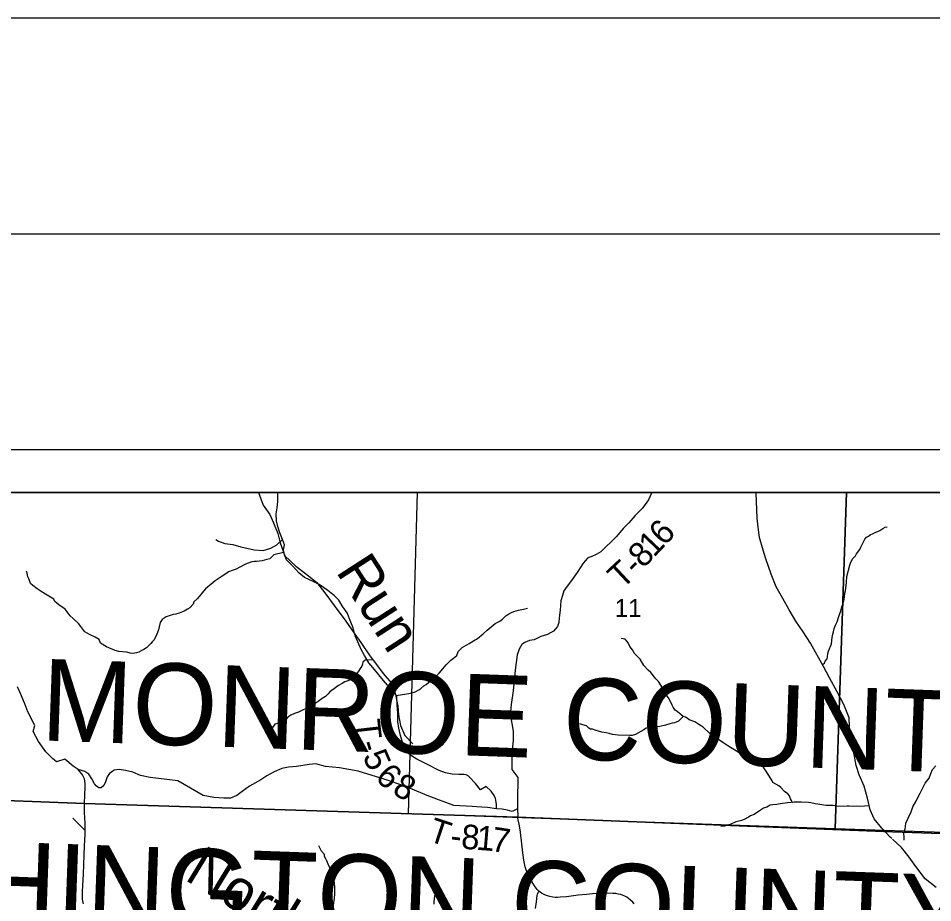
# Model space of a CAD drawing. Extents: x 6.3 to 40.3, y 9 to 31.
# Drawn here: x 10.464 to 12.585, y 28.995 to 31.046 of the extents above; entities that cross this region are included whole.
import ezdxf

# ---------------------------------------------------------------- set-up
doc = ezdxf.new("R2010")
doc.units = 0
for name, color, linetype in [('Default', 7, 'Continuous'), ('GM_X_Corporation', 7, 'Continuous'), ('GM_X_County_Text', 7, 'Continuous'), ('GM_X_Minor_River', 7, 'Continuous'), ('GM_X_Minor_River_Text', 7, 'Continuous'), ('GM_X_Section_Text', 7, 'Continuous'), ('GM_X_Township_Road', 7, 'Continuous'), ('GM_X_Township_Road_Text', 7, 'Continuous'), ('SH_Border', 7, 'Continuous'), ('SH_Cut_Line', 7, 'Continuous'), ('SH_Data', 7, 'Continuous')]:
    doc.layers.add(name, color=color, linetype=linetype)

msp = doc.modelspace()

# ---------------------------------------------------------------- linework, layer by layer
at = {"layer": 'Default'}
for points in [[(13.1323, 29.9457), (8.4446, 29.9457), (8.4446, 27.9161), (8.9627, 27.9002), (9.9314, 27.8681), (10.145, 27.8635), (10.7129, 27.8423), (11.7175, 27.8106), (12.5872, 27.7766), (13.0625, 27.76), (13.0974, 28.6191), (13.1136, 29.1637), (13.1156, 29.231), (13.116, 29.2473), (13.13, 29.8856)], [(12.9998, 29.9457), (8.4446, 29.9457), (8.4446, 29.2958), (8.8673, 29.2829), (9.8361, 29.2507), (10.0496, 29.2462), (10.6176, 29.225), (11.6221, 29.1933), (12.4918, 29.1593), (12.9672, 29.1426)]]:
    msp.add_lwpolyline(points, close=True, dxfattribs=at)
msp.add_lwpolyline([(12.9672, 29.1426), (12.4918, 29.1593), (11.6221, 29.1933), (10.6176, 29.225), (10.0496, 29.2462), (9.8361, 29.2507), (8.8673, 29.2829), (8.4446, 29.2958), (8.4446, 23.1457)], dxfattribs=at)
at = {"layer": 'GM_X_Corporation'}
for points in [[(12.3853, 29.9457), (11.3893, 29.9457), (11.3683, 29.2019), (12.3591, 29.1669)], [(13, 29.9457), (12.3853, 29.9457), (12.3591, 29.1669), (12.9779, 29.1462), (12.9985, 29.8988)]]:
    msp.add_lwpolyline(points, close=True, dxfattribs=at)
at = {"layer": 'GM_X_Minor_River'}
for points in [[(11.0214, 29.9457), (11.0322, 29.9167), (11.0478, 29.8951), (11.0565, 29.8759), (11.0667, 29.851), (11.0716, 29.8295), (11.0826, 29.7993), (11.1083, 29.7755), (11.1303, 29.7585), (11.1568, 29.737), (11.178, 29.7105), (11.1973, 29.6837), (11.2238, 29.6475), (11.245, 29.6177), (11.2586, 29.5981), (11.2798, 29.5675), (11.2953, 29.5471), (11.3105, 29.5263), (11.3301, 29.5037), (11.3396, 29.4772), (11.3449, 29.4504), (11.346, 29.4304), (11.3506, 29.4055), (11.3612, 29.3821), (11.3797, 29.3629)], [(12.2376, 29.7003), (12.222, 29.7275), (12.2103, 29.7566), (12.1982, 29.7924), (12.1921, 29.8121), (12.1831, 29.8419), (12.18, 29.8657), (12.1778, 29.8864), (12.1759, 29.9446), (12.1759, 29.9457)], [(12.3298, 29.5468), (12.3338, 29.5506), (12.336, 29.5552), (12.34, 29.5606), (12.3414, 29.5648), (12.3416, 29.5724), (12.3434, 29.5782), (12.3502, 29.5954), (12.3518, 29.6099), (12.3536, 29.6172), (12.355, 29.6225), (12.3567, 29.6309), (12.3599, 29.6382), (12.3636, 29.6463), (12.3664, 29.6558), (12.3689, 29.6627), (12.3717, 29.6715), (12.3742, 29.6811), (12.3767, 29.6868), (12.3792, 29.6945), (12.3805, 29.7036), (12.3811, 29.7124), (12.3829, 29.7177), (12.3855, 29.7372), (12.3863, 29.7509), (12.3926, 29.7772), (12.3943, 29.7818), (12.3994, 29.7922), (12.4057, 29.7988), (12.4083, 29.8038), (12.416, 29.8139), (12.4182, 29.8196), (12.424, 29.83), (12.4276, 29.8381), (12.4317, 29.8427), (12.4362, 29.8451), (12.4403, 29.8478), (12.4467, 29.8506), (12.4531, 29.8538), (12.4576, 29.8558), (12.4625, 29.8582), (12.4696, 29.8629), (12.4745, 29.8653), (12.4798, 29.8666)], [(11.0798, 29.8069), (11.0569, 29.8012), (11.048, 29.7923), (11.0405, 29.7906), (11.0299, 29.7877), (11.0235, 29.7864), (11.017, 29.7862), (11.0114, 29.7857), (11.0061, 29.7849), (10.991, 29.78), (10.9786, 29.7728), (10.9696, 29.7685), (10.9602, 29.7652), (10.9523, 29.762), (10.9456, 29.7577), (10.9351, 29.7506), (10.9306, 29.7475), (10.9213, 29.7408), (10.9116, 29.7337), (10.8989, 29.7228), (10.8937, 29.717), (10.8837, 29.7046), (10.8793, 29.6992), (10.8719, 29.6926), (10.8697, 29.6872), (10.8623, 29.6787), (10.8571, 29.6751), (10.8492, 29.6708), (10.8375, 29.6663), (10.8296, 29.6639), (10.8239, 29.663), (10.8123, 29.6589), (10.8077, 29.6577), (10.798, 29.6518), (10.7936, 29.6448), (10.7915, 29.6345), (10.7894, 29.6273), (10.7855, 29.6177), (10.7797, 29.6042), (10.7748, 29.6), (10.7715, 29.5957), (10.7667, 29.5903), (10.7619, 29.586), (10.7559, 29.5821), (10.7495, 29.5785), (10.7439, 29.5757), (10.7386, 29.5741), (10.7344, 29.5732), (10.7295, 29.5727), (10.7238, 29.5737), (10.7158, 29.5755), (10.7063, 29.5764), (10.6976, 29.577), (10.6892, 29.5794), (10.6692, 29.5881), (10.655, 29.5969), (10.6522, 29.6052), (10.6426, 29.6103), (10.6299, 29.6169), (10.6191, 29.6227), (10.6098, 29.635), (10.6039, 29.6421), (10.5915, 29.6536), (10.5849, 29.6599), (10.5728, 29.6756), (10.5586, 29.6852), (10.5489, 29.6933), (10.5465, 29.6986), (10.5273, 29.7103), (10.5153, 29.7176), (10.508, 29.7224), (10.4984, 29.7302), (10.493, 29.735), (10.4897, 29.744), (10.4865, 29.7508), (10.4848, 29.7591), (10.4832, 29.7633)], [(12.4901, 29.1437), (12.4866, 29.1469), (12.4669, 29.1677), (12.4495, 29.1896), (12.4401, 29.21), (12.4336, 29.2375), (12.4261, 29.2651), (12.4143, 29.2911), (12.4075, 29.3126), (12.4033, 29.3383), (12.3969, 29.3697), (12.3924, 29.4025), (12.3916, 29.4233), (12.3791, 29.4546), (12.3636, 29.484), (12.3458, 29.5165), (12.3322, 29.5426), (12.3019, 29.5969), (12.2849, 29.623), (12.2678, 29.6475), (12.2519, 29.6739), (12.2376, 29.7003)], [(11.34, 29.4754), (11.3396, 29.4751), (11.3453, 29.4763), (11.351, 29.4768), (11.36, 29.4782), (11.3699, 29.4799), (11.3804, 29.4824), (11.385, 29.4837), (11.3936, 29.488), (11.3981, 29.4916), (11.4048, 29.4974), (11.4104, 29.5006), (11.4167, 29.5064), (11.4234, 29.5119), (11.4309, 29.5178), (11.4406, 29.5267), (11.4494, 29.5372), (11.4564, 29.5465), (11.4628, 29.5527), (11.4676, 29.5573), (11.4736, 29.562), (11.4818, 29.5683), (11.4842, 29.5775), (11.4939, 29.5864), (11.5104, 29.5959), (11.5201, 29.6018), (11.5291, 29.6074), (11.5422, 29.6179), (11.5518, 29.6269), (11.5701, 29.6425), (11.5813, 29.648), (11.5877, 29.6524), (11.5951, 29.6601), (11.6022, 29.6649), (11.6082, 29.6677), (11.6135, 29.6697), (11.6188, 29.6713), (11.6244, 29.673), (11.6286, 29.6738), (11.6358, 29.6755), (11.6456, 29.678)], [(12.2598, 29.2274), (12.2593, 29.2271), (12.2573, 29.2316), (12.2557, 29.2357), (12.2529, 29.2429), (12.2494, 29.247), (12.2416, 29.2525), (12.2327, 29.2618), (12.2281, 29.2655), (12.2146, 29.2736), (12.2126, 29.2777), (12.2024, 29.2934), (12.1981, 29.3009), (12.1895, 29.3137), (12.1752, 29.3228), (12.1683, 29.3265), (12.1633, 29.3298), (12.1418, 29.3384), (12.1364, 29.3425), (12.1099, 29.3582), (12.1007, 29.3645), (12.0953, 29.3682), (12.0733, 29.3821), (12.0671, 29.3877), (12.0528, 29.4018), (12.0486, 29.404), (12.0424, 29.4076), (12.0335, 29.4143), (12.0205, 29.4189), (12.0159, 29.4226), (12.0117, 29.4248), (12.0067, 29.4262), (11.9974, 29.434), (11.9928, 29.4384), (11.9878, 29.441), (11.9831, 29.4481), (11.9811, 29.453), (11.9743, 29.4673), (11.97, 29.4729), (11.9617, 29.4871), (11.9582, 29.4931), (11.9495, 29.5078), (11.9433, 29.5141), (11.9312, 29.5286), (11.925, 29.5342), (11.9149, 29.545), (11.9066, 29.5596), (11.9031, 29.5637), (11.8934, 29.5726), (11.8887, 29.5812), (11.8825, 29.5891), (11.8785, 29.597), (11.8761, 29.6011), (11.8722, 29.6056), (11.8676, 29.607), (11.8623, 29.6076)], [(11.287, 29.558), (11.2687, 29.5571), (11.2632, 29.5524), (11.2625, 29.5478), (11.2615, 29.5432), (11.2574, 29.5378), (11.2534, 29.5316), (11.2486, 29.5255), (11.2393, 29.5158), (11.2341, 29.5118), (11.2288, 29.5094), (11.222, 29.5066), (11.2157, 29.5034), (11.207, 29.4987), (11.2018, 29.4948), (11.1973, 29.4909), (11.1932, 29.4881), (11.1872, 29.4838), (11.1828, 29.4788), (11.1769, 29.4733), (11.1694, 29.4682), (11.1597, 29.4611), (11.1503, 29.4552), (11.1417, 29.4505), (11.1319, 29.4449), (11.1222, 29.4405), (11.1139, 29.4369), (11.1052, 29.4337), (11.0966, 29.4297), (11.0899, 29.425), (11.0854, 29.4203), (11.0738, 29.4136), (11.0689, 29.4112), (11.0595, 29.4084), (11.0506, 29.3964), (11.0485, 29.3918), (11.0463, 29.3875), (11.0438, 29.3822)], [(12.0061, 29.4267), (11.9959, 29.4161), (11.9903, 29.4133), (11.9861, 29.4121), (11.9809, 29.4108), (11.9752, 29.4095), (11.9658, 29.4063), (11.9526, 29.4033), (11.9461, 29.4024), (11.9367, 29.4011), (11.9325, 29.401), (11.9204, 29.3992), (11.9148, 29.3956), (11.896, 29.385), (11.8881, 29.3825), (11.8828, 29.3824), (11.8559, 29.3833), (11.8425, 29.3849), (11.8345, 29.387), (11.8276, 29.3887), (11.8177, 29.3904), (11.8101, 29.3929), (11.8048, 29.3943), (11.796, 29.3968), (11.7918, 29.3974), (11.7876, 29.3996), (11.7821, 29.4048), (11.7734, 29.4073), (11.7691, 29.4087), (11.7634, 29.4097)], [(12.5193, 29.1398), (12.5187, 29.1463), (12.5185, 29.1561), (12.5196, 29.1603), (12.521, 29.1661), (12.522, 29.171), (12.5226, 29.1802), (12.5273, 29.1883), (12.5287, 29.1932), (12.5342, 29.2028), (12.5392, 29.217), (12.5476, 29.2317), (12.5502, 29.237), (12.5563, 29.2489), (12.5647, 29.2659), (12.5676, 29.2716), (12.5772, 29.2836), (12.5811, 29.2947), (12.5844, 29.3035), (12.5921, 29.3125)], [(12.4378, 29.2197), (12.4158, 29.2177), (12.4082, 29.2183), (12.4018, 29.2181), (12.3915, 29.2183), (12.3866, 29.2185), (12.3665, 29.2181), (12.3543, 29.2201), (12.3482, 29.2199), (12.338, 29.2205), (12.333, 29.2211), (12.3189, 29.2235), (12.3125, 29.2241), (12.3026, 29.2261), (12.2972, 29.2272), (12.2798, 29.2275), (12.2726, 29.2277), (12.2642, 29.2279), (12.2559, 29.227), (12.2487, 29.2261), (12.2313, 29.2241), (12.2237, 29.2228), (12.2146, 29.2215), (12.2082, 29.2206), (12.2003, 29.2166), (12.1924, 29.2142), (12.1834, 29.2079), (12.1711, 29.1996), (12.1628, 29.1964), (12.1583, 29.1932), (12.1478, 29.1877), (12.1418, 29.1853), (12.1354, 29.1836), (12.1286, 29.1823), (12.1154, 29.1759), (12.1083, 29.1743), (12.1026, 29.1726), (12.0984, 29.1721), (12.0939, 29.1713)], [(12.5934, 29.0302), (12.5676, 29.0502), (12.546, 29.0789), (12.5305, 29.1005), (12.5127, 29.1227), (12.4916, 29.1423)], [(11.1949, 28.983), (11.1959, 28.9948), (11.197, 29.0002), (11.1977, 29.0055), (11.1984, 29.0154), (11.1986, 29.0294), (11.1974, 29.0408), (11.1954, 29.0495), (11.1938, 29.0552), (11.1926, 29.0594), (11.1903, 29.0666), (11.1867, 29.0756), (11.1829, 29.0843), (11.1797, 29.0915), (11.1774, 29.0968), (11.1747, 29.1021), (11.1743, 29.1067), (11.1674, 29.1142), (11.1611, 29.1263)], [(11.4288, 28.9916), (11.4291, 28.9969), (11.4304, 29.011), (11.4334, 29.022), (11.4348, 29.0304), (11.4344, 29.0346), (11.4339, 29.0391), (11.432, 29.0441), (11.43, 29.049), (11.4257, 29.0626)]]:
    msp.add_lwpolyline(points, dxfattribs=at)
at = {"layer": 'GM_X_Township_Road'}
for points in [[(11.5736, 29.2127), (11.5734, 29.2234), (11.5715, 29.2366), (11.5684, 29.2436), (11.561, 29.2535), (11.5499, 29.2642), (11.536, 29.2564), (11.5245, 29.2708), (11.512, 29.2852), (11.5081, 29.2891), (11.5033, 29.291), (11.4976, 29.292), (11.4861, 29.292), (11.4707, 29.2929), (11.4553, 29.2958), (11.4409, 29.3016), (11.4102, 29.3169), (11.3891, 29.3275), (11.3766, 29.3352), (11.367, 29.3419), (11.3603, 29.3535), (11.3564, 29.364), (11.3507, 29.3823), (11.3468, 29.3996), (11.3449, 29.4149), (11.3449, 29.4341), (11.343, 29.4533), (11.342, 29.4726), (11.3372, 29.4822), (11.3295, 29.4899), (11.3209, 29.4995), (11.3113, 29.51), (11.3007, 29.5235), (11.2863, 29.5398), (11.2777, 29.5513), (11.2671, 29.5677), (11.2594, 29.5821), (11.2518, 29.5994), (11.246, 29.6138), (11.2412, 29.632), (11.2354, 29.6455), (11.2268, 29.6666), (11.2172, 29.681), (11.2076, 29.6964), (11.198, 29.706), (11.1826, 29.7185), (11.1625, 29.7329), (11.148, 29.7396), (11.1279, 29.7492), (11.1154, 29.7598), (11.101, 29.7751), (11.0866, 29.7895), (11.0818, 29.8011), (11.0798, 29.8131), (11.0818, 29.8246), (11.077, 29.8371), (11.0712, 29.8525), (11.0664, 29.8669), (11.0635, 29.8803), (11.0626, 29.8967), (11.0645, 29.9101), (11.0664, 29.9255), (11.0664, 29.9428), (11.0653, 29.9457)], [(11.9337, 29.9457), (11.9261, 29.9292), (11.9123, 29.9093), (11.8954, 29.8925), (11.8801, 29.8756), (11.8678, 29.8633), (11.851, 29.8434), (11.8158, 29.8082), (11.805, 29.802), (11.7943, 29.7974), (11.7851, 29.7944), (11.7744, 29.7821), (11.7606, 29.7607), (11.7453, 29.7392), (11.7376, 29.7285), (11.7299, 29.7178), (11.7269, 29.707), (11.7223, 29.6948), (11.7208, 29.6733), (11.7192, 29.655), (11.7177, 29.6442), (11.7146, 29.635), (11.7054, 29.6243), (11.6916, 29.6166), (11.6763, 29.6121), (11.661, 29.6044), (11.6503, 29.6028), (11.6395, 29.5983), (11.6319, 29.5937), (11.6258, 29.5829), (11.6211, 29.5692), (11.6166, 29.5339), (11.612, 29.4864), (11.6074, 29.4542), (11.6058, 29.4373), (11.6074, 29.419), (11.6104, 29.4021), (11.612, 29.3914), (11.612, 29.3715), (11.6089, 29.3393), (11.6089, 29.304), (11.6226, 29.285), (11.6218, 29.2315), (11.6224, 29.2121), (11.6232, 29.1956), (11.6223, 29.1928)], [(10.9222, 29.8373), (10.9288, 29.8334), (10.9433, 29.8275), (10.9617, 29.8255), (10.9808, 29.8202), (11.0117, 29.813), (11.0327, 29.8117), (11.0505, 29.8169), (11.0643, 29.8248), (11.077, 29.8371)], [(11.6224, 29.2121), (11.6102, 29.2066), (11.5993, 29.2092), (11.5864, 29.2117), (11.5736, 29.2127), (11.5528, 29.2152), (11.5392, 29.2166), (11.5277, 29.2173), (11.5172, 29.2177), (11.4743, 29.22), (11.4167, 29.2418), (11.3606, 29.2652), (11.3154, 29.2808), (11.253, 29.2995), (11.2094, 29.3073), (11.1766, 29.3104), (11.1548, 29.3167), (11.1392, 29.3151), (11.1096, 29.3104), (11.0909, 29.3089), (11.0753, 29.3058), (11.0582, 29.2979), (11.041, 29.2886), (11.027, 29.2793), (11.0005, 29.2652), (10.9833, 29.2528), (10.9709, 29.2434), (10.9569, 29.2371), (10.9413, 29.2371), (10.9179, 29.2387), (10.8929, 29.2434), (10.8346, 29.2773), (10.8086, 29.2806), (10.77, 29.2853), (10.748, 29.29), (10.73, 29.2976), (10.713, 29.3013), (10.6983, 29.3036), (10.687, 29.302), (10.676, 29.294), (10.6707, 29.2863), (10.6667, 29.275), (10.6627, 29.2666), (10.6567, 29.261), (10.6513, 29.261), (10.6448, 29.2654), (10.6413, 29.2703), (10.6347, 29.2823), (10.628, 29.2926), (10.619, 29.299), (10.6033, 29.3036), (10.592, 29.3113), (10.572, 29.3276), (10.5532, 29.3214), (10.5438, 29.3292), (10.5282, 29.3448), (10.5111, 29.3682), (10.4986, 29.3916), (10.5026, 29.406), (10.4866, 29.4374), (10.4794, 29.4558), (10.4695, 29.4797), (10.4623, 29.4955)], [(10.6178, 29.2245), (10.6187, 29.245), (10.6197, 29.2626), (10.6197, 29.2713), (10.618, 29.282), (10.6133, 29.2913), (10.6033, 29.3036)], [(10.6196, 29.1623), (10.6195, 29.1704), (10.6193, 29.1797), (10.6186, 29.1908), (10.6177, 29.2049), (10.6176, 29.2142), (10.6178, 29.2245)], [(10.5913, 29.1905), (10.6025, 29.1788), (10.6189, 29.1629), (10.6196, 29.1623)], [(11.6713, 29.0217), (11.668, 29.0251), (11.6653, 29.0284), (11.6614, 29.034), (11.6574, 29.0404), (11.651, 29.0517), (11.6476, 29.0583), (11.6448, 29.0646), (11.6425, 29.071), (11.6403, 29.0782), (11.6386, 29.0854), (11.6372, 29.0934), (11.6348, 29.1106), (11.6322, 29.1316), (11.6291, 29.1581), (11.6276, 29.1686), (11.626, 29.1771), (11.6223, 29.1928)], [(10.6153, 28.9921), (10.6146, 28.9955), (10.614, 28.9991), (10.6137, 29.0022), (10.6133, 29.009), (10.6134, 29.0196), (10.6141, 29.0345), (10.6153, 29.0611), (10.6162, 29.0822), (10.617, 29.1058), (10.6181, 29.1263), (10.6193, 29.153), (10.6196, 29.1623)], [(11.6638, 28.9809), (11.666, 28.9969), (11.6669, 29.0042), (11.6681, 29.0112), (11.6688, 29.0144), (11.6699, 29.0181), (11.6706, 29.0199), (11.6713, 29.0217)], [(11.8931, 28.9918), (11.8893, 28.9959), (11.8848, 29.0002), (11.88, 29.0041), (11.8754, 29.0072), (11.871, 29.0097), (11.8671, 29.0115), (11.8619, 29.0135), (11.8558, 29.0149), (11.8503, 29.0158), (11.8429, 29.0164), (11.8317, 29.0167), (11.8183, 29.0164), (11.7965, 29.0152), (11.782, 29.014), (11.7629, 29.0119), (11.7358, 29.0086), (11.7209, 29.0072), (11.7147, 29.0069), (11.7097, 29.007), (11.7042, 29.0075), (11.6968, 29.0089), (11.6914, 29.0104), (11.6868, 29.0121), (11.6823, 29.0142), (11.6779, 29.0166), (11.6744, 29.0191), (11.6713, 29.0217)]]:
    msp.add_lwpolyline(points, dxfattribs=at)
at = {"layer": 'SH_Border'}
msp.add_lwpolyline([(7.8446, 30.5457), (39.8446, 30.5457), (39.8446, 9.5457), (7.8446, 9.5457)], close=True, dxfattribs=at)
at = {"layer": 'SH_Cut_Line'}
msp.add_lwpolyline([(6.3446, 9.0457), (40.3446, 9.0457), (40.3446, 31.0457), (6.3446, 31.0457)], close=True, dxfattribs=at)
for points in [[(15.2446, 29.9457), (8.4446, 29.9457), (8.4446, 29.2958), (8.8673, 29.2829), (9.8361, 29.2507), (10.0496, 29.2462), (10.6176, 29.225), (11.6221, 29.1933), (12.4918, 29.1593), (12.9672, 29.1426)], [(12.9672, 29.1426), (12.4918, 29.1593), (11.6221, 29.1933), (10.6176, 29.225), (10.0496, 29.2462), (9.8361, 29.2507), (8.8673, 29.2829), (8.4446, 29.2958), (8.4446, 23.1457)]]:
    msp.add_lwpolyline(points, dxfattribs=at)
at = {"layer": 'SH_Data'}
for p, q in [((8.3446, 30.0457), (15.3446, 30.0457)), ((8.4446, 29.9457), (15.2446, 29.9457))]:
    msp.add_line(p, q, dxfattribs=at)

# ---------------------------------------------------------------- texts
at = {"layer": 'GM_X_County_Text'}
for s, p in [('MONROE COUNTY', (10.5153, 29.3712)), ('WASHINGTON COUNTY', (9.7904, 28.9692))]:
    msp.add_text(s, height=0.189394, rotation=357.9773, dxfattribs=at).set_placement(p)
at = {"layer": 'GM_X_Minor_River_Text'}
for s, rotation, p in [('Run', 302.847, (11.1995, 29.7631)), ('North', 328.5956, (10.8475, 29.0494))]:
    msp.add_text(s, height=0.0947, rotation=rotation, dxfattribs=at).set_placement(p)
at = {"layer": 'GM_X_Section_Text'}
msp.add_text('11', height=0.04186, rotation=0, dxfattribs=at).set_placement((11.8477, 29.6571))
at = {"layer": 'GM_X_Township_Road_Text'}
for s, rotation, p in [('6', 47.4343, (11.9632, 29.8201)), ('1', 46.4984, (11.9384, 29.794)), ('8', 46.4092, (11.9142, 29.7685)), ('T', 43.0162, (11.8644, 29.7201)), ('-', 46.1586, (11.8979, 29.7515)), ('T', 276.5411, (11.2462, 29.417)), ('5', 293.263, (11.2624, 29.335)), ('-', 286.5969, (11.2533, 29.3641)), ('6', 315.5041, (11.2897, 29.2831)), ('8', 332.3348, (11.3293, 29.2479)), ('T', 341.8524, (11.4119, 29.1391)), ('8', 355.7808, (11.4902, 29.1203)), ('1', 355.4001, (11.525, 29.1177)), ('7', 351.3812, (11.5589, 29.115)), ('-', 353.3721, (11.4645, 29.1232))]:
    msp.add_text(s, height=0.0568, rotation=rotation, dxfattribs=at).set_placement(p)

doc.saveas('drawing.dxf')
